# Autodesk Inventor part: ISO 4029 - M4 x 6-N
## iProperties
Created: 2011-01
Part Number: ISO 4029 - M4 x 6-N
Document SubType Name: Modeling
Designer: eric
Density: 1 g/cm^3
Mass: 0.0603815 g
Surface Area: 1.0753 cm^2
Volume: 0.0603815 cm^3
Author: eric
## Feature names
1. Base1
